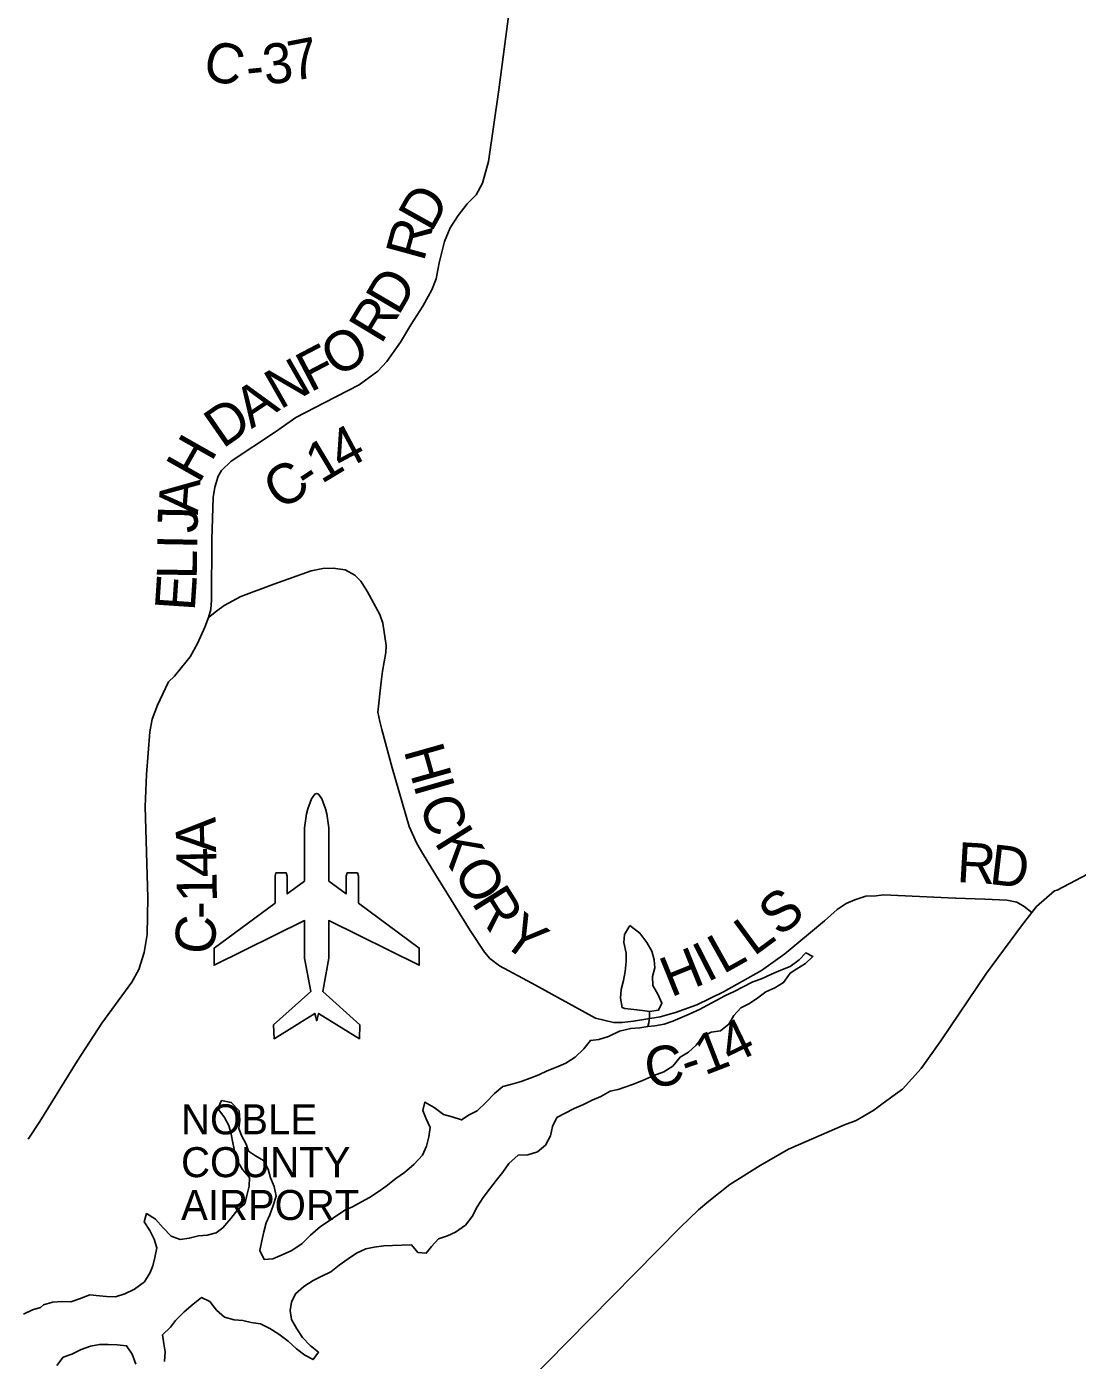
# Model space of a CAD drawing. Extents: x 0 to 34, y 0 to 22.
# Drawn here: x 26.755 to 28.244, y 11.27 to 13.16 of the extents above; entities that cross this region are included whole.
import ezdxf

# ---------------------------------------------------------------- set-up
doc = ezdxf.new("R2010")
doc.units = 0
for name, color, linetype in [('Default', 7, 'Continuous'), ('GM_X_County_Road_Text', 7, 'Continuous'), ('GM_X_Major_River', 7, 'Continuous'), ('GM_X_State_Route', 7, 'Continuous')]:
    doc.layers.add(name, color=color, linetype=linetype)

msp = doc.modelspace()

# ---------------------------------------------------------------- linework, layer by layer
at = {"layer": 'Default'}
for points in [[(27.0125, 12.3226), (27.0159, 12.3343), (27.017, 12.3479), (27.0173, 12.4339), (27.0192, 12.493), (27.0214, 12.5074), (27.0263, 12.5229), (27.0312, 12.5312), (27.0448, 12.5441), (27.1075, 12.5859), (27.1362, 12.606), (27.1774, 12.6273), (27.2261, 12.6527), (27.2525, 12.6717), (27.2654, 12.6857), (27.285, 12.713), (27.2993, 12.7377), (27.3163, 12.7638), (27.3291, 12.7869), (27.3355, 12.8025), (27.3397, 12.8252), (27.3472, 12.8555), (27.3551, 12.8752), (27.3664, 12.8923), (27.3793, 12.9089), (27.3921, 12.9218), (27.4011, 12.9381), (27.4098, 12.9692), (27.4241, 13.0703), (27.4425, 13.2112)], [(28.0719, 11.9253), (27.9697, 11.9297), (27.9591, 11.9286), (27.9448, 11.9278), (27.9289, 11.9229), (27.9168, 11.9175), (27.904, 11.9088), (27.8858, 11.8929), (27.8296, 11.8462), (27.7967, 11.8227), (27.7427, 11.7923), (27.705, 11.7737), (27.6747, 11.7631), (27.6528, 11.757), (27.6154, 11.7509), (27.5992, 11.749), (27.5867, 11.749), (27.5614, 11.755), (27.471, 11.8048), (27.4253, 11.8294), (27.4113, 11.8396), (27.4037, 11.8487), (27.3837, 11.8793), (27.336, 11.9561), (27.3159, 11.989), (27.308, 12.0026), (27.297, 12.0265), (27.2731, 12.1097), (27.2583, 12.1643), (27.2553, 12.1752), (27.2526, 12.1885), (27.2575, 12.2317), (27.2594, 12.2468), (27.2639, 12.2733), (27.2646, 12.2832), (27.2597, 12.3146), (27.2555, 12.3271), (27.2381, 12.3592), (27.2286, 12.3744), (27.2199, 12.3827), (27.2063, 12.3903), (27.1893, 12.3929), (27.1746, 12.3921), (27.158, 12.3887), (27.1054, 12.37), (27.0586, 12.3525), (27.0348, 12.34), (27.0239, 12.332), (27.0125, 12.3226)], [(26.7568, 11.5834), (26.7736, 11.6085), (26.8265, 11.6941), (26.8612, 11.7479), (26.9038, 11.8059), (26.9136, 11.8241), (26.9212, 11.848), (26.9257, 11.8737), (26.9264, 11.9256), (26.9229, 12.0551), (26.9247, 12.1002), (26.9292, 12.1608), (26.9329, 12.1789), (26.9405, 12.1986), (26.948, 12.2145), (26.9559, 12.2316), (26.9642, 12.2396), (26.9744, 12.2521), (26.9865, 12.2672), (26.9971, 12.2858), (27.0076, 12.3089), (27.0125, 12.3226)], [(28.18, 11.9048), (28.1692, 11.9134), (28.1587, 11.9194), (28.1443, 11.9224), (28.1133, 11.9235), (28.072, 11.9253), (28.0719, 11.9253)], [(27.6102, 11.8863), (27.6024, 11.8737), (27.6014, 11.8624), (27.6049, 11.8473), (27.6047, 11.8352), (27.6033, 11.8211), (27.6008, 11.8083), (27.5979, 11.7957), (27.5969, 11.7832), (27.5989, 11.77), (27.6027, 11.7685)], [(27.6027, 11.7685), (27.6156, 11.7675), (27.6281, 11.7658), (27.6379, 11.7644), (27.6507, 11.7664), (27.6555, 11.7763), (27.6497, 11.7891), (27.6428, 11.8011), (27.6423, 11.814), (27.6456, 11.8262), (27.6443, 11.8379), (27.6412, 11.8499), (27.6342, 11.8624), (27.6243, 11.8755), (27.6102, 11.8863)], [(27.6102, 11.8863), (27.6243, 11.8755), (27.6342, 11.8624), (27.6412, 11.8499), (27.6443, 11.8379), (27.6456, 11.8262), (27.6423, 11.814), (27.6428, 11.8011), (27.6497, 11.7891), (27.6555, 11.7763), (27.6507, 11.7664), (27.6379, 11.7644)], [(27.582, 11.6514), (27.5933, 11.6538), (27.6031, 11.6573), (27.614, 11.6608), (27.6272, 11.6662), (27.6438, 11.6736), (27.6581, 11.6791), (27.6708, 11.6872), (27.6813, 11.6998), (27.6933, 11.7067), (27.7041, 11.7167), (27.7138, 11.7289), (27.7255, 11.7354), (27.7387, 11.7371), (27.7503, 11.7463), (27.7574, 11.7589), (27.7675, 11.7696), (27.7795, 11.7758), (27.7915, 11.7838), (27.8027, 11.7923), (27.8155, 11.7981), (27.8279, 11.8054), (27.8372, 11.8188), (27.847, 11.8249), (27.859, 11.8323), (27.8695, 11.8422), (27.8596, 11.8478), (27.8499, 11.8375), (27.8375, 11.8282), (27.824, 11.8232), (27.8108, 11.8173), (27.7965, 11.8108), (27.7845, 11.8065), (27.7705, 11.7995), (27.7578, 11.7929), (27.7446, 11.7867), (27.7333, 11.7806), (27.7194, 11.7728), (27.7097, 11.7678), (27.6942, 11.7608), (27.6811, 11.755), (27.6709, 11.7507), (27.6585, 11.7464), (27.6453, 11.744), (27.6355, 11.7432), (27.6242, 11.7415), (27.6113, 11.7406), (27.5955, 11.7367), (27.5797, 11.7289), (27.5661, 11.725), (27.5541, 11.7234), (27.5447, 11.7115), (27.5324, 11.6997), (27.5193, 11.6912), (27.5061, 11.6854), (27.4929, 11.6803), (27.4809, 11.6745), (27.4688, 11.6698), (27.4557, 11.6655), (27.4425, 11.6616), (27.43, 11.6581), (27.418, 11.6481), (27.4061, 11.6358), (27.3937, 11.6236), (27.3821, 11.6178), (27.3712, 11.6109), (27.3579, 11.6153), (27.3458, 11.6185), (27.3325, 11.6282), (27.3195, 11.636), (27.3163, 11.6243), (27.3213, 11.6126), (27.3267, 11.6002), (27.325, 11.5869), (27.3217, 11.5736), (27.3158, 11.5607), (27.3042, 11.5481), (27.2907, 11.5362), (27.278, 11.5277), (27.2645, 11.517), (27.2547, 11.5097), (27.2408, 11.5008), (27.2296, 11.4947), (27.2168, 11.4877), (27.207, 11.4835), (27.1961, 11.4765), (27.1822, 11.4669), (27.1713, 11.46), (27.1571, 11.4477), (27.1455, 11.4359), (27.1309, 11.4259), (27.117, 11.4197), (27.1038, 11.4142), (27.0917, 11.413), (27.0855, 11.4258), (27.0884, 11.4394), (27.0909, 11.4523), (27.0946, 11.4648), (27.0994, 11.4762), (27.1042, 11.4895), (27.1086, 11.5028)], [(27.6379, 11.7644), (27.6281, 11.7658), (27.6156, 11.7675), (27.6027, 11.7685)], [(27.6355, 11.7432), (27.6369, 11.7484), (27.6378, 11.757), (27.6379, 11.7644)]]:
    msp.add_lwpolyline(points, dxfattribs=at)
msp.add_lwpolyline([(27.1069, 11.9182), (27.0206, 11.8544), (27.0206, 11.83), (27.1489, 11.8932), (27.1489, 11.84), (27.1575, 11.7928), (27.1047, 11.7455), (27.1055, 11.7259), (27.1633, 11.7618), (27.166, 11.7513), (27.1687, 11.7618), (27.2265, 11.7259), (27.2273, 11.7455), (27.1745, 11.7928), (27.183, 11.84), (27.183, 11.8932), (27.3114, 11.83), (27.3114, 11.8544), (27.2251, 11.9182), (27.2251, 11.9563), (27.2238, 11.9609), (27.2091, 11.9609), (27.2077, 11.9563), (27.2077, 11.9311), (27.183, 11.9493), (27.183, 11.9493), (27.183, 12.0245), (27.1805, 12.0444), (27.1785, 12.0515), (27.1734, 12.066), (27.1687, 12.0724), (27.166, 12.0735), (27.1633, 12.0724), (27.1586, 12.066), (27.1535, 12.0515), (27.1514, 12.0444), (27.1489, 12.0245), (27.1489, 11.9493), (27.1242, 11.9311), (27.1242, 11.9563), (27.1229, 11.9609), (27.1082, 11.9609), (27.1069, 11.9563)], close=True, dxfattribs=at)
at = {"layer": 'GM_X_Major_River'}
for points in [[(27.582, 11.6514), (27.5933, 11.6538), (27.6031, 11.6573), (27.614, 11.6608), (27.6272, 11.6662), (27.6438, 11.6736), (27.6581, 11.6791), (27.6708, 11.6872), (27.6813, 11.6998), (27.6933, 11.7067), (27.7041, 11.7167), (27.7138, 11.7289), (27.7255, 11.7354), (27.7387, 11.7371), (27.7503, 11.7463), (27.7574, 11.7589), (27.7675, 11.7696), (27.7795, 11.7758), (27.7915, 11.7838), (27.8027, 11.7923), (27.8155, 11.7981), (27.8279, 11.8054), (27.8372, 11.8188), (27.847, 11.8249), (27.859, 11.8323), (27.8695, 11.8422), (27.8596, 11.8478), (27.8499, 11.8375), (27.8375, 11.8282), (27.824, 11.8232), (27.8108, 11.8173), (27.7965, 11.8108), (27.7845, 11.8065), (27.7705, 11.7995), (27.7578, 11.7929), (27.7446, 11.7867), (27.7333, 11.7806), (27.7194, 11.7728), (27.7097, 11.7678), (27.6942, 11.7608), (27.6811, 11.755), (27.6709, 11.7507), (27.6585, 11.7464), (27.6453, 11.744), (27.6355, 11.7432)], [(27.6355, 11.7432), (27.6242, 11.7415), (27.6113, 11.7406), (27.5955, 11.7367), (27.5797, 11.7289), (27.5661, 11.725), (27.5541, 11.7234), (27.5447, 11.7115), (27.5324, 11.6997), (27.5193, 11.6912), (27.5061, 11.6854), (27.4929, 11.6803), (27.4809, 11.6745), (27.4688, 11.6698), (27.4557, 11.6655), (27.4425, 11.6616), (27.43, 11.6581), (27.418, 11.6481), (27.4061, 11.6358), (27.3937, 11.6236), (27.3821, 11.6178), (27.3712, 11.6109), (27.3579, 11.6153), (27.3458, 11.6185), (27.3325, 11.6282), (27.3195, 11.636), (27.3163, 11.6243), (27.3213, 11.6126), (27.3267, 11.6002), (27.325, 11.5869), (27.3217, 11.5736), (27.3158, 11.5607), (27.3042, 11.5481), (27.2907, 11.5362), (27.278, 11.5277), (27.2645, 11.517), (27.2547, 11.5097), (27.2408, 11.5008), (27.2296, 11.4947), (27.2168, 11.4877), (27.207, 11.4835), (27.1961, 11.4765), (27.1822, 11.4669), (27.1713, 11.46), (27.1571, 11.4477), (27.1455, 11.4359), (27.1309, 11.4259), (27.117, 11.4197), (27.1038, 11.4142), (27.0917, 11.413), (27.0855, 11.4258), (27.0884, 11.4394), (27.0909, 11.4523), (27.0946, 11.4648), (27.0994, 11.4762), (27.1042, 11.4895), (27.1086, 11.5028)], [(26.9504, 11.2684), (26.951, 11.282), (26.9494, 11.2934), (26.9473, 11.3062), (26.9589, 11.3173), (26.966, 11.3268), (26.978, 11.3391), (26.9911, 11.3498), (27.0027, 11.359), (27.0145, 11.3535), (27.0241, 11.3411), (27.0351, 11.3314), (27.0488, 11.3277), (27.0612, 11.3264), (27.073, 11.3238), (27.0862, 11.3217), (27.0995, 11.3154), (27.1121, 11.3072), (27.1254, 11.2975), (27.1376, 11.2863), (27.1494, 11.2774), (27.1608, 11.2711), (27.1686, 11.2817), (27.1568, 11.2914), (27.1461, 11.3027), (27.1377, 11.3147), (27.1304, 11.3279), (27.1284, 11.3407), (27.1305, 11.3528), (27.136, 11.3646), (27.148, 11.3746), (27.1612, 11.3834), (27.1732, 11.3892), (27.186, 11.3954), (27.198, 11.405), (27.2107, 11.4142), (27.2224, 11.4219), (27.2355, 11.4281), (27.2476, 11.4305), (27.2612, 11.4322), (27.2737, 11.4327), (27.2869, 11.4332), (27.3005, 11.4338), (27.3096, 11.4229), (27.3214, 11.4219), (27.3288, 11.4314), (27.3389, 11.4425), (27.3513, 11.4468), (27.363, 11.4518), (27.3769, 11.4615), (27.3866, 11.474), (27.3936, 11.4877), (27.4022, 11.5007), (27.4108, 11.5125), (27.4204, 11.5251), (27.4298, 11.5366), (27.4383, 11.5492), (27.4518, 11.561), (27.4654, 11.5612), (27.479, 11.5655), (27.4902, 11.5751), (27.4973, 11.5884), (27.5005, 11.6013), (27.5064, 11.6142), (27.5181, 11.6204), (27.5312, 11.627), (27.5444, 11.6328), (27.5564, 11.639), (27.5689, 11.644), (27.582, 11.6514)], [(27.1086, 11.5028), (27.1058, 11.5164), (27.1007, 11.5288), (27.0972, 11.5409), (27.0906, 11.5533), (27.0792, 11.56), (27.0694, 11.5667), (27.0658, 11.5765), (27.0593, 11.5886), (27.0558, 11.5987), (27.0572, 11.6101), (27.0559, 11.6237), (27.0448, 11.6357), (27.0312, 11.6382), (27.026, 11.6272), (27.0352, 11.6144), (27.0414, 11.6027), (27.0449, 11.5907), (27.0473, 11.5782), (27.0501, 11.565), (27.0536, 11.5522), (27.0609, 11.5405), (27.0709, 11.5293), (27.0702, 11.5168), (27.067, 11.5039), (27.0641, 11.4921), (27.0543, 11.4837), (27.0443, 11.4711), (27.0331, 11.4581), (27.0233, 11.4508), (27.0109, 11.4473), (26.9984, 11.4464), (26.9852, 11.4432), (26.9724, 11.4412), (26.9599, 11.446), (26.9484, 11.4579), (26.9377, 11.4703), (26.9248, 11.4781), (26.9215, 11.4664), (26.9292, 11.454), (26.9357, 11.4419), (26.9393, 11.4298), (26.9364, 11.4158), (26.9339, 11.4041), (26.9298, 11.3946), (26.922, 11.3816), (26.9077, 11.3712), (26.8942, 11.3643), (26.8806, 11.3603), (26.8678, 11.3606), (26.858, 11.3616), (26.8443, 11.363), (26.8297, 11.3575), (26.8176, 11.3532), (26.8051, 11.3535), (26.7915, 11.3526), (26.7787, 11.349)], [(26.7787, 11.349), (26.7746, 11.3452), (26.7633, 11.3417), (26.7502, 11.3355)], [(26.7974, 11.263), (26.8067, 11.2744), (26.8188, 11.2791), (26.8319, 11.2857), (26.8451, 11.29), (26.8583, 11.2924), (26.8704, 11.2925), (26.8832, 11.2919), (26.8965, 11.2905), (26.9045, 11.2789), (26.9096, 11.2649)]]:
    msp.add_lwpolyline(points, dxfattribs=at)
at = {"layer": 'GM_X_State_Route'}
msp.add_lwpolyline([(27.3842, 11.1566), (27.5211, 11.296), (27.6814, 11.4582), (27.7075, 11.4833), (27.7222, 11.4959), (27.752, 11.5191), (27.7947, 11.5463), (27.8351, 11.5696), (27.9145, 11.6041), (27.9311, 11.6098), (27.956, 11.6246), (27.9674, 11.633), (27.9866, 11.6473), (27.9964, 11.6545), (28.0232, 11.6837), (28.0511, 11.723), (28.1158, 11.8188), (28.1651, 11.8857), (28.18, 11.9048), (28.1866, 11.9134), (28.2123, 11.9354), (28.2161, 11.9364), (28.2679, 11.964)], dxfattribs=at)

# ---------------------------------------------------------------- texts
at = {"layer": 'Default'}
for s, p in [('NOBLE', (26.9737, 11.5904)), ('COUNTY', (26.9737, 11.5297)), ('AIRPORT', (26.9737, 11.469))]:
    msp.add_text(s, height=0.04253, rotation=0, dxfattribs=at).set_placement(p)
at = {"layer": 'GM_X_County_Road_Text'}
for s, rotation, p in [('C', 346.1427, (27.0019, 13.0875)), ('3', 7.5945, (27.0933, 13.0774)), ('7', 10.961, (27.1315, 13.0826)), ('-', 5.7938, (27.0682, 13.0748)), ('D', 60.8601, (27.3287, 12.8674)), ('R', 74.6904, (27.3177, 12.8258)), ('D', 59.6092, (27.2818, 12.7492)), ('R', 58.9422, (27.2574, 12.7087)), ('O', 32.4395, (27.1954, 12.6616)), ('F', 27.6382, (27.157, 12.6412)), ('N', 29.7336, (27.1142, 12.6168)), ('A', 33.7143, (27.0736, 12.5896)), ('D', 34.7974, (27.0328, 12.5613)), ('4', 28.1013, (27.2019, 12.5291)), ('H', 60.4932, (26.9995, 12.5115)), ('1', 30.9468, (27.1726, 12.5115)), ('C', 33.7788, (27.1151, 12.4732)), ('-', 33.2614, (27.1537, 12.4991)), ('A', 85.5001, (26.9975, 12.4679)), ('J', 88.9276, (26.997, 12.4422)), ('I', 89.0008, (26.9966, 12.4189)), ('L', 89.0684, (26.9959, 12.3766)), ('E', 86.1745, (26.993, 12.3311)), ('H', 285.7638, (27.2891, 12.1345)), ('I', 285.8691, (27.3027, 12.0863)), ('C', 289.8281, (27.3104, 12.0599)), ('A', 91.1547, (27.0235, 11.99)), ('K', 302.0071, (27.3319, 12.0042)), ('R', 356.6963, (28.0727, 11.948)), ('D', 353.3223, (28.1183, 11.9454)), ('4', 91.0325, (27.0242, 11.955)), ('O', 301.4386, (27.3583, 11.9621)), ('1', 90.6734, (27.0246, 11.9197)), ('R', 302.0772, (27.3847, 11.9189)), ('S', 39.5448, (27.8225, 11.869)), ('-', 89.7324, (27.0245, 11.8954)), ('Y', 323.1999, (27.4248, 11.8627)), ('C', 85.1586, (27.0203, 11.844)), ('L', 36.4778, (27.7858, 11.8418)), ('L', 29.2122, (27.7422, 11.8168)), ('H', 21.984, (27.6682, 11.7842)), ('I', 27.132, (27.7195, 11.8052)), ('4', 25.8309, (27.7533, 11.6882)), ('C', 9.5162, (27.636, 11.655)), ('1', 21.1367, (27.7161, 11.6736)), ('-', 18.9463, (27.6918, 11.6652))]:
    msp.add_text(s, height=0.0567, rotation=rotation, dxfattribs=at).set_placement(p)

doc.saveas('drawing.dxf')
